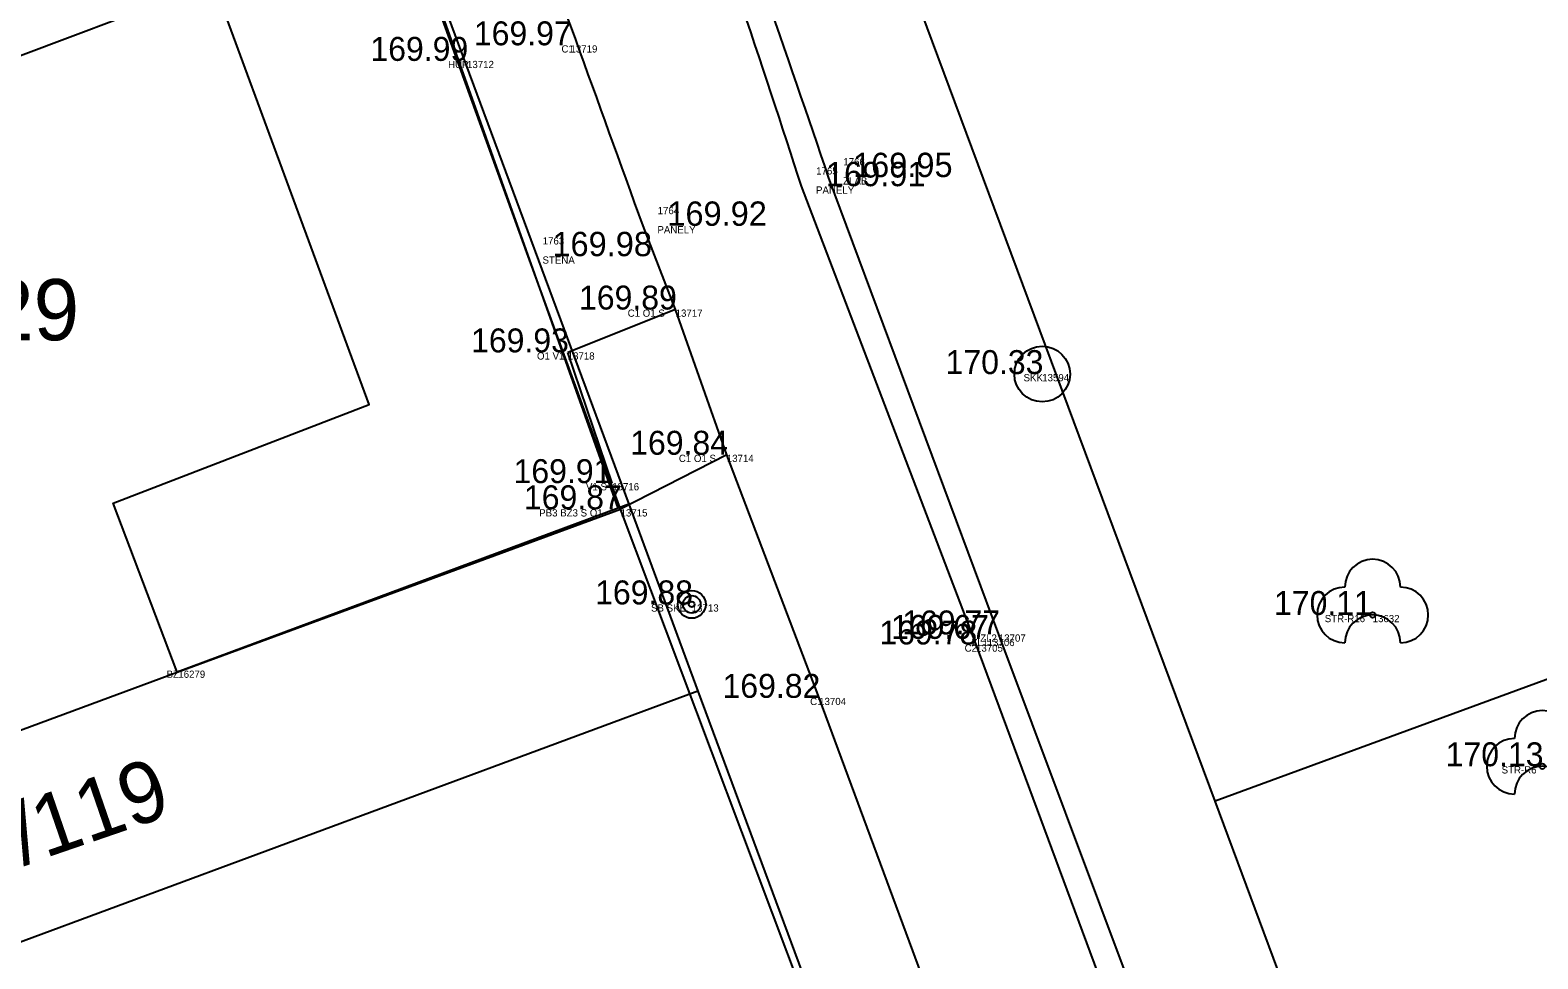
# Model space of a CAD drawing. Extents: x -566117 to -565580, y -1202428 to -1201938.
# Drawn here: x -565881.85 to -565854.75, y -1202200.91 to -1202184.22 of the extents above; entities that cross this region are included whole.
import ezdxf

# ---------------------------------------------------------------- set-up
doc = ezdxf.new("R2010")
doc.units = 0
for name, color, linetype in [('(Construction)', 7, 'Continuous'), ('_0', 7, 'Continuous'), ('Bod', 7, 'Continuous'), ('BUDOVY_MĚŘ (Construction)', 7, 'Continuous'), ('CIZÍ_NADZEM', 7, 'Continuous'), ('Implicitní', 7, 'Continuous'), ('Kanalizace', 7, 'Continuous'), ('Katastr', 7, 'Continuous'), ('Kod', 7, 'Continuous'), ('Oplocení', 7, 'Continuous'), ('Výška', 7, 'Continuous'), ('ZELEŇ', 7, 'Continuous'), ('Zpevněné plohy', 7, 'Continuous'), ('Číslo', 7, 'Continuous')]:
    doc.layers.add(name, color=color, linetype=linetype)

# ---------------------------------------------------------------- blocks, each defined once
blk = doc.blocks.new('A$C69D74C1E')
at = {"layer": 'Katastr'}
for p, q in [((204.38, -129.64), (181.01, -66.83)), ((289.63, -98.3), (204.38, -129.64)), ((193.65, -124.37), (188.17, -109)), ((188.17, -109), (193.84, -124.3)), ((193.84, -124.3), (195.08, -127.66)), ((172.89, -132.06), (185.72, -127.32)), ((195.08, -127.66), (174.19, -135.4)), ((195.08, -127.66), (199.29, -139.02)), ((221, -174.32), (204.38, -129.64))]:
    blk.add_line(p, q, dxfattribs=at)
for points in [[(185.72, -127.32), (184.57, -124.28), (189.17, -122.51), (186.38, -114.93), (182.1, -116.54), (180.46, -111.85)], [(193.84, -124.3), (193.65, -124.37), (185.72, -127.32)]]:
    blk.add_lwpolyline(points, dxfattribs=at)
blk.add_text('2437/29', height=1.1, dxfattribs=at).set_placement((178.64, -121.353))
blk.add_text('2437/119', height=1.1, rotation=19, dxfattribs=at).set_placement((179.861, -131.863))
blk = doc.blocks.new('POINT_DISPLAY')
at = {"layer": 'Implicitní'}
blk.add_line((0, 0), (0, 0), dxfattribs=at)
blk = doc.blocks.new('STROM')
at = {"layer": 'ZELEŇ'}
blk.add_circle((0, 0), 0.05, dxfattribs=at)
for centre, start, end in [((0, 0.5), 0, 180), ((-0.5, 0), 90, 270), ((0.5, 0), 270, 90), ((0, -0.5), 0, 180)]:
    blk.add_arc(centre, 0.5, start, end, dxfattribs=at)
blk = doc.blocks.new('SAK')
at = {"layer": 'Kanalizace'}
blk.add_circle((0, 0), 0.5, dxfattribs=at)
blk = doc.blocks.new('SLB')
at = {"layer": 'CIZÍ_NADZEM'}
for radius in [0.25, 0.158, 0.05]:
    blk.add_circle((0, 0), radius, dxfattribs=at)

msp = doc.modelspace()

# ---------------------------------------------------------------- linework, layer by layer
at = {"layer": '(Construction)'}
for p, q in [((-565872.902, -1202188.281), (-565877.534, -1202175.451)), ((-565871.24, -1202192.83), (-565872.902, -1202188.281)), ((-565879.21, -1202195.76), (-565871.24, -1202192.83))]:
    msp.add_line(p, q, dxfattribs=at)
at = {"layer": '_0'}
msp.add_line((-565871.39, -1202192.36), (-565872.19, -1202190.01), dxfattribs=at)
at = {"layer": 'BUDOVY_MĚŘ (Construction)'}
msp.add_line((-565872.902, -1202188.281), (-565877.534, -1202175.451), dxfattribs=at)
at = {"layer": 'Oplocení'}
msp.add_line((-565866.84, -1202204.53), (-565871.24, -1202192.83), dxfattribs=at)
at = {"layer": 'Zpevněné plohy'}
for p, q in [((-565864.44, -1202195.08), (-565867.499, -1202186.859)), ((-565864.85, -1202195.26), (-565867.985, -1202187.023)), ((-565870.25, -1202189.24), (-565870.836, -1202187.735)), ((-565870.25, -1202189.24), (-565872.19, -1202190.01)), ((-565869.33, -1202191.85), (-565870.25, -1202189.24)), ((-565869.33, -1202191.85), (-565871.24, -1202192.83)), ((-565867.67, -1202196.22), (-565869.33, -1202191.85)), ((-565861.94, -1202201.76), (-565864.44, -1202195.08)), ((-565862.38, -1202201.91), (-565864.85, -1202195.26)), ((-565864.83, -1202203.88), (-565867.67, -1202196.22))]:
    msp.add_line(p, q, dxfattribs=at)
for points in [[(-565870.836, -1202187.735), (-565871.649, -1202185.484), (-565873.23, -1202181.104), (-565875.832, -1202174.081), (-565878.484, -1202166.972), (-565882.365, -1202157.37), (-565885.162, -1202149.181), (-565888.939, -1202140.01), (-565891.203, -1202133.383), (-565894.098, -1202125.895), (-565896.244, -1202119.433), (-565898.532, -1202113.67), (-565899.938, -1202109.875), (-565900.462, -1202108.462)], [(-565867.499, -1202186.859), (-565868.227, -1202184.73), (-565869.99, -1202179.574), (-565872.768, -1202172.617), (-565876.258, -1202163.128), (-565879.319, -1202155.06), (-565882.772, -1202146.042), (-565886.289, -1202136.562), (-565889.156, -1202128.944), (-565890.966, -1202124.137)], [(-565867.985, -1202187.023), (-565868.68, -1202184.897), (-565870.36, -1202179.758), (-565873.248, -1202172.838), (-565876.611, -1202163.269), (-565879.858, -1202155.218), (-565883.166, -1202146.125), (-565884.833, -1202141.634), (-565885.905, -1202138.743)]]:
    msp.add_open_spline(points, degree=3, dxfattribs=at)

# ---------------------------------------------------------------- block references
at = {"layer": 'Bod'}
for p in [(-565872.14, -1202184.49), (-565874, -1202184.77), (-565867.499, -1202186.859), (-565867.985, -1202187.023), (-565870.836, -1202187.735), (-565872.902, -1202188.281), (-565870.25, -1202189.24), (-565872.19, -1202190.01), (-565863.66, -1202190.4), (-565869.33, -1202191.85), (-565871.39, -1202192.36), (-565871.24, -1202192.83), (-565869.96, -1202194.54), (-565857.72, -1202194.73), (-565864.44, -1202195.08), (-565864.85, -1202195.26), (-565864.64, -1202195.16), (-565879.19, -1202195.73), (-565867.67, -1202196.22)]:
    msp.add_blockref('POINT_DISPLAY', p, dxfattribs=at)
at = {"layer": 'CIZÍ_NADZEM'}
msp.add_blockref('SLB', (-565869.96, -1202194.54), dxfattribs=at)
at = {"layer": 'Implicitní'}
msp.add_blockref('A$C69D74C1E', (-566064.93, -1202068.44), dxfattribs=at)
at = {"layer": 'Kanalizace'}
msp.add_blockref('SAK', (-565863.66, -1202190.4), dxfattribs=at)
at = {"layer": 'ZELEŇ'}
for p in [(-565857.72, -1202194.73), (-565854.67, -1202197.45)]:
    msp.add_blockref('STROM', p, dxfattribs=at)

# ---------------------------------------------------------------- texts
at = {"layer": 'Kod'}
for s, p in [('C1', (-565872.302, -1202184.62)), ('HUP', (-565874.341, -1202184.9)), ('ZLAB', (-565867.239, -1202186.993)), ('PANELY', (-565867.726, -1202187.157)), ('PANELY', (-565870.577, -1202187.87)), ('STENA', (-565872.643, -1202188.415)), ('C1 O1 S', (-565871.112, -1202189.37)), ('O1 V1', (-565872.742, -1202190.14)), ('SKK', (-565863.995, -1202190.53)), ('C1 O1 S', (-565870.192, -1202191.98)), ('V1 S', (-565871.862, -1202192.49)), ('PB3 BZ3 S O1', (-565872.702, -1202192.96)), ('SB SKE', (-565870.692, -1202194.67)), ('STR-R16', (-565858.581, -1202194.86)), ('ZL2', (-565864.775, -1202195.21)), ('C2', (-565865.055, -1202195.39)), ('ZL1', (-565864.932, -1202195.29)), ('BZ', (-565879.401, -1202195.86)), ('C1', (-565867.832, -1202196.35)), ('STR-R6', (-565855.401, -1202197.58))]:
    msp.add_text(s, height=0.13, dxfattribs=at).set_placement(p)
at = {"layer": 'Výška'}
for s, height, p in [('169.97 ', 0.43, (-565873.877, -1202184.49)), ('169.99 ', 0.43, (-565875.737, -1202184.77)), ('169.95', 0.4375, (-565867.061, -1202186.859)), ('169.91', 0.4375, (-565867.548, -1202187.023)), ('169.92', 0.4375, (-565870.399, -1202187.735)), ('169.98', 0.4375, (-565872.465, -1202188.281)), ('169.89 ', 0.43, (-565871.987, -1202189.24)), ('169.93 ', 0.43, (-565873.927, -1202190.01)), ('170.33 ', 0.43, (-565865.397, -1202190.4)), ('169.84 ', 0.43, (-565871.067, -1202191.85)), ('169.91 ', 0.43, (-565873.163, -1202192.36)), ('169.87 ', 0.43, (-565872.977, -1202192.83)), ('169.88 ', 0.43, (-565871.697, -1202194.54)), ('170.11 ', 0.43, (-565859.493, -1202194.73)), ('169.78 ', 0.43, (-565866.587, -1202195.26)), ('169.67 ', 0.43, (-565866.377, -1202195.16)), ('169.77 ', 0.43, (-565866.177, -1202195.08)), ('169.82 ', 0.43, (-565869.407, -1202196.22)), ('170.13 ', 0.43, (-565856.407, -1202197.45))]:
    msp.add_text(s, height=height, dxfattribs=at).set_placement(p)
at = {"layer": 'Číslo'}
for s, p in [('13719', (-565872.14, -1202184.62)), ('13712', (-565874, -1202184.9)), ('1765', (-565867.723, -1202186.813)), ('1766', (-565867.236, -1202186.649)), ('1764', (-565870.574, -1202187.526)), ('1763', (-565872.64, -1202188.071)), ('13717', (-565870.25, -1202189.37)), ('13718', (-565872.19, -1202190.14)), ('13594', (-565863.66, -1202190.53)), ('13714', (-565869.33, -1202191.98)), ('13716', (-565871.39, -1202192.49)), ('13715', (-565871.24, -1202192.96)), ('13713', (-565869.96, -1202194.67)), ('13632', (-565857.72, -1202194.86)), ('13707', (-565864.44, -1202195.21)), ('13705', (-565864.85, -1202195.39)), ('13706', (-565864.64, -1202195.29)), ('16279', (-565879.19, -1202195.86)), ('13704', (-565867.67, -1202196.35))]:
    msp.add_text(s, height=0.13, dxfattribs=at).set_placement(p)

doc.saveas('drawing.dxf')
